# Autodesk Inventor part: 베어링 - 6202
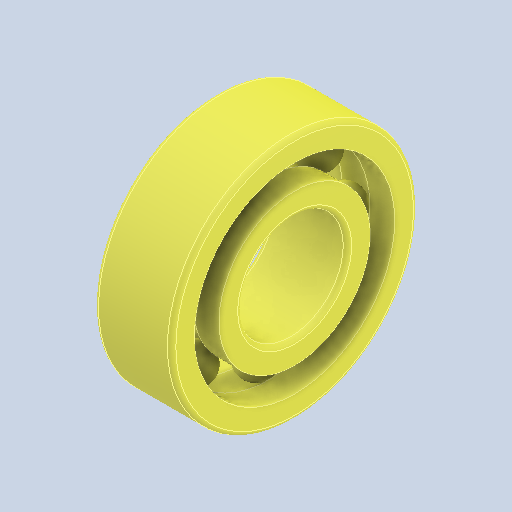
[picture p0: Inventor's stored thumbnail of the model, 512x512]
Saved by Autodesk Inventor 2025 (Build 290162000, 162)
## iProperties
Created: 2024-07
Part Number: 베어링 - 6202
Material: 강, 연강
Description: 깊은 그루브 볼 베어링
Document SubType Name: Modeling
Designer: parkm
Density: 7.86 g/cm^3
Appearance: 기본값
Author: jhkim
Sending System: Autodesk Inventor 2025
Preprocessor: ST-DEVELOPER v20
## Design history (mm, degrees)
feature "Solid1"
feature "Solid1:1"
feature "Solid1:2"
feature "Solid1:3"
feature "Solid1:4"
feature "Solid1:5"
feature "Solid1:6"
feature "Solid1:7"
feature "Solid1:8"
feature "Solid1:9"
node "솔리드1"
node "솔리드2"
node "솔리드3"
node "솔리드4"
node "솔리드5"
node "솔리드6"
node "솔리드7"
node "솔리드8"
node "솔리드9"
node "솔리드10"
